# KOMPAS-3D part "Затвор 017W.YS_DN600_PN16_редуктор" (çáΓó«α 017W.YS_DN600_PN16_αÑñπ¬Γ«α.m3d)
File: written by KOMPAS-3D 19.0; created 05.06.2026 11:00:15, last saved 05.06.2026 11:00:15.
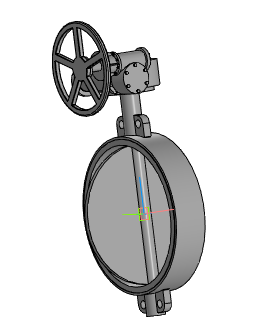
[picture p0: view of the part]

Document properties: Автор: Энергия; Полное имя файла: ..\..\..\3d для проектировщиков\x.x Тип 017W.Y(S) Затвор дисковый поворотный межфланцевый\Затвор 017W.Y(S)_DN50-DN1200_редуктор\Затвор 017W.YS_DN600_PN16_редуктор.a3d

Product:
- Part/product: Затвор 017W.YS_DN600_PN16_редуктор
    Масса: 244.021

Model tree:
1. Операция без истории:1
